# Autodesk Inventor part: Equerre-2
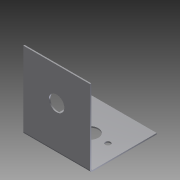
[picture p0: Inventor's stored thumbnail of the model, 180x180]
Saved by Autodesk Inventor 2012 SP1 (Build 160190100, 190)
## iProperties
Created: 2012-08
Part Number: Equerre-2
Material: Par défaut
Document SubType Name: Tôlerie
Designer: Bruno
Density: 1 g/cm^3
Flat Pattern Width: 2.6 cm
Flat Pattern Length: 5.5131 cm
Flat Pattern Area: 14.3341 cm^2
Sheet Metal Rule: Par défaut_mm
Sheet Metal Width: 26,000 mm
Sheet Metal Length: 55,131 mm
Sheet Metal Area: 1433,405 mm^2
Author: Bruno
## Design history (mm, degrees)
node "Face2"
  sketch "Esquisse1"
    geometry: L1 (0, 0)-(26, 0); L2 (26, 0)-(26, 26); L3 (26, 26)-(0, 26); L4 (0, 26)-(0, 0)
    constraints: 8 end point, 2 parallel, 1 horizontal, 1 perpendicular
    dimensions: "d0" = 26 distance of L3.end L2.end; "d1" = 26 distance of L1.end L2.end
node "Bord tombé1"
sketch "Esquisse3"
  geometry: L1 (0, 26)-(0, 1) reference; L2 (-26, 26)-(0, 26) reference; 4 further points
  dimensions: "d14" = 13 distance from line of point (-13, 13) L1; "d15" = 14 distance of point (-6, 13) point (-20, 13); "d16" = 13 distance from line of point (-6, 13) L2; "d17" = 13 distance from line of L2 point (-13, 13); "d18" = 7 distance of point (-20, 13) point (-13, 13)
hole "Perçage1" sketch "Esquisse3" at (-20, 13), (-6, 13), (-13, 13) diameter "d19" = 2; stored, may be unused: countersink angle "d23" = 90 deg, drill point angle "d25" = 118 deg; dims "d20" = 6, "d21" = 4, "d22" = 2, "d24" = 0.5 (= Epaisseur)
sketch "Esquisse4"
  geometry: 2 further points
hole "Perçage2" sketch "Esquisse4" at (-13, 13) diameter "d31" = 6.5; stored, may be unused: countersink angle "d35" = 90 deg, drill point angle "d37" = 118 deg; dims "d32" = 6, "d33" = 4, "d34" = 2, "d36" = 0.5 (= Epaisseur)
sketch "Esquisse5"
  geometry: L1 (26, 0)-(26, -29) reference; L2 (0, 0)-(26, 0) reference; 2 further points
  dimensions: "d38" = 13 distance from line of L2 point (13, -13); "d39" = 13 distance from line of L1 point (13, -13)
hole "Perçage3" sketch "Esquisse5" at (13, -13) diameter "d40" = 6; stored, may be unused: countersink angle "d44" = 90 deg, drill point angle "d46" = 118 deg; dims "d41" = 6, "d42" = 4, "d43" = 2, "d45" = 0.5 (= Epaisseur)
node "Solide2"
feature "Plaque2" dims "Epaisseur" = 0.5 (derived)
sketch "Esquisse2"
  geometry: L1 (0, 30)-(-26, 30); L2 (-26, 30)-(-26, 0); 2 other entities
  constraints: 4 end point, 4 other
feature "Plaque3" dims "d4" = 0.5 (= LargeurGrugeage), "d5" = 0.25 (= ProfondeurGrugeage), "d6" = 1 (= RestesMinimum), "d7" = 0.5 (= RayonPli), "d8" = 30, "d9" = 90 deg, "d10" = 0.5 (= RayonPli), "d11" = 2 (= TailleGrugeage), "d12" = 0.5 (= TailleJeu), "d13" = 0.5 (= TailleRayonJacobi), "Epaisseur" = 0.5 (derived), "JeuJointure" = 0.01
feature "Pli1" dims "d4" = 0.5 (= LargeurGrugeage), "d5" = 0.25 (= ProfondeurGrugeage), "d6" = 1 (= RestesMinimum), "d7" = 0.5 (= RayonPli), "d8" = 30, "d9" = 90 deg, "d10" = 0.5 (= RayonPli), "Epaisseur" = 0.5 (derived), "JeuJointure" = 0.01
feature "Coin1" dims "d8" = 30, "d9" = 90 deg, "d11" = 2 (= TailleGrugeage), "d12" = 0.5 (= TailleJeu), "d13" = 0.5 (= TailleRayonJacobi)
feature "Définition1"
other parameters: "FacteurX" = 4.4, "RayonPli" = 0.5 (= Epaisseur), "LargeurGrugeage" = 0.5 (= Epaisseur), "ProfondeurGrugeage" = 0.25 (= 0.5 x Epaisseur), "TailleGrugeage" = 2 (= 4 x Epaisseur), "RestesMinimum" = 1 (= 2 x Epaisseur), "Rayondetransition" = 0.5 (= RayonPli), "TailleRayonJacobi" = 0.5 (= RayonPli), "TailleJeu" = 0.5 (= Epaisseur), "d2" = 0.5 (= RayonPli), "d3" = 0.5 (= RayonPli), "Epaisseur" = 0.5, "LargeurGrugeage" = 0.5, "ProfondeurGrugeage" = 0.25, "RayonPli" = 0.5, "Rayondetransition" = 0.5, "RestesMinimum" = 1, "TailleGrugeage" = 2, "TailleJeu" = 0.5, "TailleRayonJacobi" = 0.5
